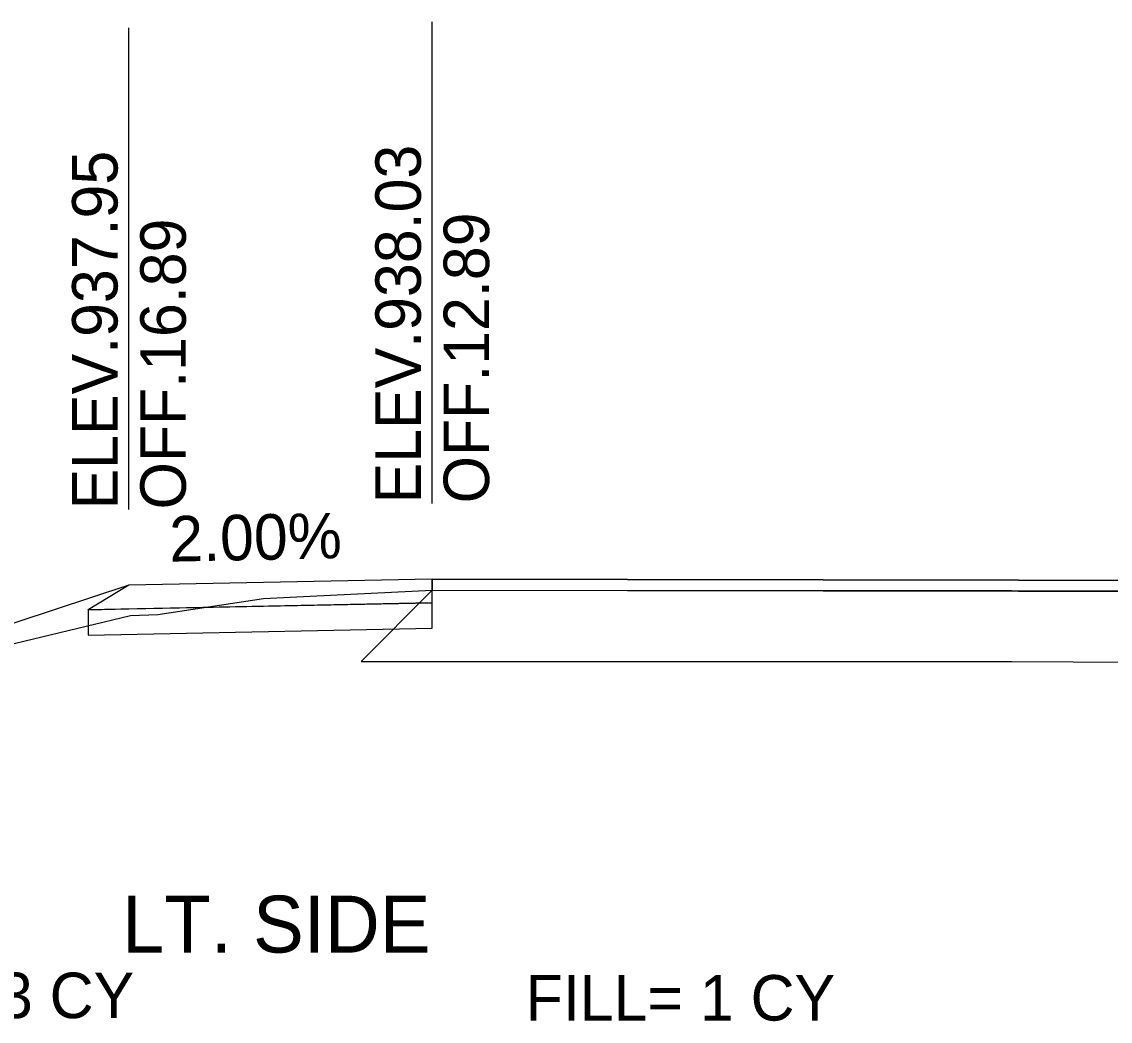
# Model space of a CAD drawing. Extents: x -4 to 359, y 0 to 1436.
# Drawn here: x 234.2 to 248.55, y 817.17 to 830.35 of the extents above; entities that cross this region are included whole.
import ezdxf

# ---------------------------------------------------------------- set-up
doc = ezdxf.new("R2010")
doc.units = 0
for name, color, linetype in [('XS-Existing subsurface-pavement', 7, 'Continuous'), ('XS-Existing surface-ground', 7, 'Continuous'), ('XS-Proposed Finish Grade', 7, 'Continuous'), ('XS-Proposed subsurface-aggregate layer 1', 7, 'Continuous'), ('XS-Proposed surface-ground', 7, 'Continuous'), ('XS-Proposed surface-pavement', 7, 'Continuous'), ('XS-Proposed surface-shoulder', 7, 'Continuous'), ('XS-Text-earthwork labels', 7, 'Continuous'), ('XS-Text-pavement elevation', 7, 'Continuous'), ('XS-Text-profile report', 7, 'Continuous'), ('XS-Text-shoulder slope', 7, 'Continuous'), ('XS-Text-tie offset', 7, 'Continuous')]:
    doc.layers.add(name, color=color, linetype=linetype)

msp = doc.modelspace()

# ---------------------------------------------------------------- linework, layer by layer
at = {"layer": 'XS-Existing subsurface-pavement'}
for p, q in [((239.613, 822.857), (238.676, 821.92)), ((238.676, 821.92), (247.255, 821.916)), ((247.252, 821.916), (252.497, 821.899))]:
    msp.add_line(p, q, dxfattribs=at)
at = {"layer": 'XS-Existing surface-ground'}
for p, q in [((238.001, 822.778), (239.613, 822.857)), ((239.613, 822.857), (247.255, 822.853)), ((247.255, 822.853), (252.5, 822.836)), ((235.992, 822.536), (237.389, 822.748)), ((237.389, 822.748), (238.001, 822.778)), ((235.632, 822.524), (235.992, 822.536)), ((230.472, 821.289), (235.632, 822.524))]:
    msp.add_line(p, q, dxfattribs=at)
at = {"layer": 'XS-Proposed Finish Grade'}
for points in [[(239.613, 823.003), (235.613, 822.923)], [(239.613, 823.003), (252.5, 822.982), (262.928, 822.947)]]:
    msp.add_lwpolyline(points, dxfattribs=at)
at = {"layer": 'XS-Proposed subsurface-aggregate layer 1'}
for points in [[(239.613, 822.691), (235.074, 822.6)], [(239.613, 822.357), (239.613, 822.691)], [(235.074, 822.6), (235.074, 822.267)], [(235.074, 822.267), (239.613, 822.357)]]:
    msp.add_lwpolyline(points, dxfattribs=at)
at = {"layer": 'XS-Proposed surface-ground'}
msp.add_lwpolyline([(235.613, 822.923), (231.164, 821.455)], dxfattribs=at)
at = {"layer": 'XS-Proposed surface-pavement'}
for points in [[(239.613, 823.003), (239.613, 822.857)], [(262.928, 822.947), (252.5, 822.982), (239.613, 823.003)], [(239.613, 822.857), (252.5, 822.836), (262.928, 822.802)]]:
    msp.add_lwpolyline(points, dxfattribs=at)
at = {"layer": 'XS-Proposed surface-shoulder'}
for points in [[(239.613, 823.003), (235.613, 822.923), (235.074, 822.6)], [(239.613, 822.691), (239.613, 823.003)], [(235.074, 822.6), (235.613, 822.611), (239.613, 822.691)]]:
    msp.add_lwpolyline(points, dxfattribs=at)
at = {"layer": 'XS-Text-tie offset'}
for p, q in [((239.613, 824.003), (239.613, 830.353)), ((235.613, 823.923), (235.613, 830.275))]:
    msp.add_line(p, q, dxfattribs=at)

# ---------------------------------------------------------------- texts
at = {"layer": 'XS-Text-earthwork labels'}
for s, height, p in [('LT. SIDE', 0.75, (235.522, 818.08)), (' CUT= 3 CY           ', 0.6, (231.335, 817.215)), ('FILL= 1 CY           ', 0.6, (240.846, 817.183))]:
    msp.add_text(s, height=height, dxfattribs=at).set_placement(p)
at = {"layer": 'XS-Text-pavement elevation'}
for s, p in [('ELEV.937.95', (235.463, 823.923)), ('ELEV.938.03', (239.463, 824.003)), ('OFF.16.89', (236.363, 823.923)), ('OFF.12.89', (240.363, 824.003))]:
    msp.add_text(s, height=0.6, rotation=90, dxfattribs=at).set_placement(p)
at = {"layer": 'XS-Text-profile report'}
for s, p in [('Pvmt_Surf_Asph_T2_L', (239.597, 823.002)), ('Shldr_Surf_Asph_T1', (235.598, 822.922)), ('Pvmt_Surf_Asph_T_L', (239.598, 822.857)), ('Shldr_Surf_Asph_B12', (239.597, 822.69)), ('Shldr_Surf_Asph_B2', (235.059, 822.599)), ('Shldr_Surf_Asph_B1', (235.598, 822.61)), ('Agg_Layer_1_B1', (235.063, 822.266)), ('Agg_Layer_1_B', (239.602, 822.357))]:
    msp.add_text(s, height=0.00167, dxfattribs=at).set_placement(p)
at = {"layer": 'XS-Text-shoulder slope'}
msp.add_text('2.00%', height=0.6, rotation=1.1458, dxfattribs=at).set_placement((236.151, 823.234))

doc.saveas('drawing.dxf')
